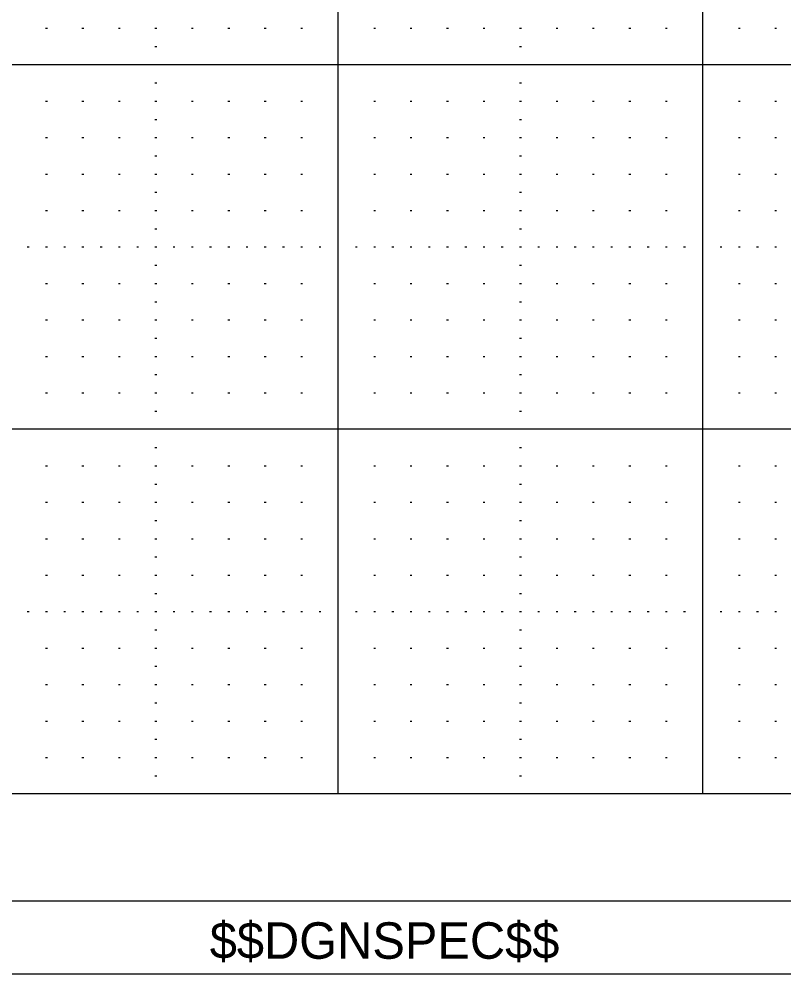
# Model space of a CAD drawing. Extents: x -1.3 to 32.1, y -0.2 to 20.7.
# Drawn here: x 27.87 to 29.967, y -0.2 to 2.418 of the extents above; entities that cross this region are included whole.
import ezdxf

# ---------------------------------------------------------------- set-up
doc = ezdxf.new("R2010")
doc.units = 0
for name, color, linetype in [('Level 1', 7, 'Continuous'), ('Level 37', 7, 'Continuous'), ('Level 4', 7, 'Continuous'), ('Level 48', 7, 'Continuous'), ('Level 5', 7, 'Continuous'), ('Level 62', 7, 'Continuous'), ('Level 63', 7, 'Continuous')]:
    doc.layers.add(name, color=color, linetype=linetype)

msp = doc.modelspace()

# ---------------------------------------------------------------- linework, layer by layer
at = {"layer": 'Level 1'}
msp.add_line((31.617, -0.001), (-0.001, -0.001), dxfattribs=at)
at = {"layer": 'Level 37'}
msp.add_line((30.746, 0.2935), (2.464, 0.2935), dxfattribs=at)
at = {"layer": 'Level 4'}
for p, q in [((28.745, 0.293), (28.745, 10.293)), ((29.745, 0.293), (29.745, 10.293)), ((31.617, 2.293), (-0.001, 2.293)), ((31.617, 1.293), (-0.001, 1.293)), ((31.617, 0.293), (2.463, 0.293))]:
    msp.add_line(p, q, dxfattribs=at)
at = {"layer": 'Level 5'}
for p, q in [((27.9425, 2.393), (27.9475, 2.393)), ((28.0425, 2.393), (28.0475, 2.393)), ((28.1425, 2.393), (28.1475, 2.393)), ((28.2425, 2.393), (28.2475, 2.393)), ((28.3425, 2.393), (28.3475, 2.393)), ((28.4425, 2.393), (28.4475, 2.393)), ((28.5425, 2.393), (28.5475, 2.393)), ((28.6425, 2.393), (28.6475, 2.393)), ((28.8425, 2.393), (28.8475, 2.393)), ((28.9425, 2.393), (28.9475, 2.393)), ((29.0425, 2.393), (29.0475, 2.393)), ((29.1425, 2.393), (29.1475, 2.393)), ((29.2425, 2.393), (29.2475, 2.393)), ((29.3425, 2.393), (29.3475, 2.393)), ((29.4425, 2.393), (29.4475, 2.393)), ((29.5425, 2.393), (29.5475, 2.393)), ((29.6425, 2.393), (29.6475, 2.393)), ((29.8425, 2.393), (29.8475, 2.393)), ((29.9425, 2.393), (29.9475, 2.393)), ((28.2425, 2.343), (28.2475, 2.343)), ((29.2425, 2.343), (29.2475, 2.343)), ((28.2425, 2.243), (28.2475, 2.243)), ((29.2425, 2.243), (29.2475, 2.243)), ((27.9425, 2.193), (27.9475, 2.193)), ((28.0425, 2.193), (28.0475, 2.193)), ((28.1425, 2.193), (28.1475, 2.193)), ((28.2425, 2.193), (28.2475, 2.193)), ((28.3425, 2.193), (28.3475, 2.193)), ((28.4425, 2.193), (28.4475, 2.193)), ((28.5425, 2.193), (28.5475, 2.193)), ((28.6425, 2.193), (28.6475, 2.193)), ((28.8425, 2.193), (28.8475, 2.193)), ((28.9425, 2.193), (28.9475, 2.193)), ((29.0425, 2.193), (29.0475, 2.193)), ((29.1425, 2.193), (29.1475, 2.193)), ((29.2425, 2.193), (29.2475, 2.193)), ((29.3425, 2.193), (29.3475, 2.193)), ((29.4425, 2.193), (29.4475, 2.193)), ((29.5425, 2.193), (29.5475, 2.193)), ((29.6425, 2.193), (29.6475, 2.193)), ((29.8425, 2.193), (29.8475, 2.193)), ((29.9425, 2.193), (29.9475, 2.193)), ((28.2425, 2.143), (28.2475, 2.143)), ((29.2425, 2.143), (29.2475, 2.143)), ((27.9425, 2.093), (27.9475, 2.093)), ((28.0425, 2.093), (28.0475, 2.093)), ((28.1425, 2.093), (28.1475, 2.093)), ((28.2425, 2.093), (28.2475, 2.093)), ((28.3425, 2.093), (28.3475, 2.093)), ((28.4425, 2.093), (28.4475, 2.093)), ((28.5425, 2.093), (28.5475, 2.093)), ((28.6425, 2.093), (28.6475, 2.093)), ((28.8425, 2.093), (28.8475, 2.093)), ((28.9425, 2.093), (28.9475, 2.093)), ((29.0425, 2.093), (29.0475, 2.093)), ((29.1425, 2.093), (29.1475, 2.093)), ((29.2425, 2.093), (29.2475, 2.093)), ((29.3425, 2.093), (29.3475, 2.093)), ((29.4425, 2.093), (29.4475, 2.093)), ((29.5425, 2.093), (29.5475, 2.093)), ((29.6425, 2.093), (29.6475, 2.093)), ((29.8425, 2.093), (29.8475, 2.093)), ((29.9425, 2.093), (29.9475, 2.093)), ((28.2425, 2.043), (28.2475, 2.043)), ((29.2425, 2.043), (29.2475, 2.043)), ((27.9425, 1.993), (27.9475, 1.993)), ((28.0425, 1.993), (28.0475, 1.993)), ((28.1425, 1.993), (28.1475, 1.993)), ((28.2425, 1.993), (28.2475, 1.993)), ((28.3425, 1.993), (28.3475, 1.993)), ((28.4425, 1.993), (28.4475, 1.993)), ((28.5425, 1.993), (28.5475, 1.993)), ((28.6425, 1.993), (28.6475, 1.993)), ((28.8425, 1.993), (28.8475, 1.993)), ((28.9425, 1.993), (28.9475, 1.993)), ((29.0425, 1.993), (29.0475, 1.993)), ((29.1425, 1.993), (29.1475, 1.993)), ((29.2425, 1.993), (29.2475, 1.993)), ((29.3425, 1.993), (29.3475, 1.993)), ((29.4425, 1.993), (29.4475, 1.993)), ((29.5425, 1.993), (29.5475, 1.993)), ((29.6425, 1.993), (29.6475, 1.993)), ((29.8425, 1.993), (29.8475, 1.993)), ((29.9425, 1.993), (29.9475, 1.993)), ((28.2425, 1.943), (28.2475, 1.943)), ((29.2425, 1.943), (29.2475, 1.943)), ((27.9425, 1.893), (27.9475, 1.893)), ((28.0425, 1.893), (28.0475, 1.893)), ((28.1425, 1.893), (28.1475, 1.893)), ((28.2425, 1.893), (28.2475, 1.893)), ((28.3425, 1.893), (28.3475, 1.893)), ((28.4425, 1.893), (28.4475, 1.893)), ((28.5425, 1.893), (28.5475, 1.893)), ((28.6425, 1.893), (28.6475, 1.893)), ((28.8425, 1.893), (28.8475, 1.893)), ((28.9425, 1.893), (28.9475, 1.893)), ((29.0425, 1.893), (29.0475, 1.893)), ((29.1425, 1.893), (29.1475, 1.893)), ((29.2425, 1.893), (29.2475, 1.893)), ((29.3425, 1.893), (29.3475, 1.893)), ((29.4425, 1.893), (29.4475, 1.893)), ((29.5425, 1.893), (29.5475, 1.893)), ((29.6425, 1.893), (29.6475, 1.893)), ((29.8425, 1.893), (29.8475, 1.893)), ((29.9425, 1.893), (29.9475, 1.893)), ((28.2425, 1.843), (28.2475, 1.843)), ((29.2425, 1.843), (29.2475, 1.843)), ((27.8925, 1.793), (27.8975, 1.793)), ((27.9425, 1.793), (27.9475, 1.793)), ((27.9925, 1.793), (27.9975, 1.793)), ((28.0425, 1.793), (28.0475, 1.793)), ((28.0925, 1.793), (28.0975, 1.793)), ((28.1425, 1.793), (28.1475, 1.793)), ((28.1925, 1.793), (28.1975, 1.793)), ((28.2425, 1.793), (28.2475, 1.793)), ((28.2925, 1.793), (28.2975, 1.793)), ((28.3425, 1.793), (28.3475, 1.793)), ((28.3925, 1.793), (28.3975, 1.793)), ((28.4425, 1.793), (28.4475, 1.793)), ((28.4925, 1.793), (28.4975, 1.793)), ((28.5425, 1.793), (28.5475, 1.793)), ((28.5925, 1.793), (28.5975, 1.793)), ((28.6425, 1.793), (28.6475, 1.793)), ((28.6925, 1.793), (28.6975, 1.793)), ((28.7925, 1.793), (28.7975, 1.793)), ((28.8425, 1.793), (28.8475, 1.793)), ((28.8925, 1.793), (28.8975, 1.793)), ((28.9425, 1.793), (28.9475, 1.793)), ((28.9925, 1.793), (28.9975, 1.793)), ((29.0425, 1.793), (29.0475, 1.793)), ((29.0925, 1.793), (29.0975, 1.793)), ((29.1425, 1.793), (29.1475, 1.793)), ((29.1925, 1.793), (29.1975, 1.793)), ((29.2425, 1.793), (29.2475, 1.793)), ((29.2925, 1.793), (29.2975, 1.793)), ((29.3425, 1.793), (29.3475, 1.793)), ((29.3925, 1.793), (29.3975, 1.793)), ((29.4425, 1.793), (29.4475, 1.793)), ((29.4925, 1.793), (29.4975, 1.793)), ((29.5425, 1.793), (29.5475, 1.793)), ((29.5925, 1.793), (29.5975, 1.793)), ((29.6425, 1.793), (29.6475, 1.793)), ((29.6925, 1.793), (29.6975, 1.793)), ((29.7925, 1.793), (29.7975, 1.793)), ((29.8425, 1.793), (29.8475, 1.793)), ((29.8925, 1.793), (29.8975, 1.793)), ((29.9425, 1.793), (29.9475, 1.793)), ((28.2425, 1.743), (28.2475, 1.743)), ((29.2425, 1.743), (29.2475, 1.743)), ((27.9425, 1.693), (27.9475, 1.693)), ((28.0425, 1.693), (28.0475, 1.693)), ((28.1425, 1.693), (28.1475, 1.693)), ((28.2425, 1.693), (28.2475, 1.693)), ((28.3425, 1.693), (28.3475, 1.693)), ((28.4425, 1.693), (28.4475, 1.693)), ((28.5425, 1.693), (28.5475, 1.693)), ((28.6425, 1.693), (28.6475, 1.693)), ((28.8425, 1.693), (28.8475, 1.693)), ((28.9425, 1.693), (28.9475, 1.693)), ((29.0425, 1.693), (29.0475, 1.693)), ((29.1425, 1.693), (29.1475, 1.693)), ((29.2425, 1.693), (29.2475, 1.693)), ((29.3425, 1.693), (29.3475, 1.693)), ((29.4425, 1.693), (29.4475, 1.693)), ((29.5425, 1.693), (29.5475, 1.693)), ((29.6425, 1.693), (29.6475, 1.693)), ((29.8425, 1.693), (29.8475, 1.693)), ((29.9425, 1.693), (29.9475, 1.693)), ((28.2425, 1.643), (28.2475, 1.643)), ((29.2425, 1.643), (29.2475, 1.643)), ((27.9425, 1.593), (27.9475, 1.593)), ((28.0425, 1.593), (28.0475, 1.593)), ((28.1425, 1.593), (28.1475, 1.593)), ((28.2425, 1.593), (28.2475, 1.593)), ((28.3425, 1.593), (28.3475, 1.593)), ((28.4425, 1.593), (28.4475, 1.593)), ((28.5425, 1.593), (28.5475, 1.593)), ((28.6425, 1.593), (28.6475, 1.593)), ((28.8425, 1.593), (28.8475, 1.593)), ((28.9425, 1.593), (28.9475, 1.593)), ((29.0425, 1.593), (29.0475, 1.593)), ((29.1425, 1.593), (29.1475, 1.593)), ((29.2425, 1.593), (29.2475, 1.593)), ((29.3425, 1.593), (29.3475, 1.593)), ((29.4425, 1.593), (29.4475, 1.593)), ((29.5425, 1.593), (29.5475, 1.593)), ((29.6425, 1.593), (29.6475, 1.593)), ((29.8425, 1.593), (29.8475, 1.593)), ((29.9425, 1.593), (29.9475, 1.593)), ((28.2425, 1.543), (28.2475, 1.543)), ((29.2425, 1.543), (29.2475, 1.543)), ((27.9425, 1.493), (27.9475, 1.493)), ((28.0425, 1.493), (28.0475, 1.493)), ((28.1425, 1.493), (28.1475, 1.493)), ((28.2425, 1.493), (28.2475, 1.493)), ((28.3425, 1.493), (28.3475, 1.493)), ((28.4425, 1.493), (28.4475, 1.493)), ((28.5425, 1.493), (28.5475, 1.493)), ((28.6425, 1.493), (28.6475, 1.493)), ((28.8425, 1.493), (28.8475, 1.493)), ((28.9425, 1.493), (28.9475, 1.493)), ((29.0425, 1.493), (29.0475, 1.493)), ((29.1425, 1.493), (29.1475, 1.493)), ((29.2425, 1.493), (29.2475, 1.493)), ((29.3425, 1.493), (29.3475, 1.493)), ((29.4425, 1.493), (29.4475, 1.493)), ((29.5425, 1.493), (29.5475, 1.493)), ((29.6425, 1.493), (29.6475, 1.493)), ((29.8425, 1.493), (29.8475, 1.493)), ((29.9425, 1.493), (29.9475, 1.493)), ((28.2425, 1.443), (28.2475, 1.443)), ((29.2425, 1.443), (29.2475, 1.443)), ((27.9425, 1.393), (27.9475, 1.393)), ((28.0425, 1.393), (28.0475, 1.393)), ((28.1425, 1.393), (28.1475, 1.393)), ((28.2425, 1.393), (28.2475, 1.393)), ((28.3425, 1.393), (28.3475, 1.393)), ((28.4425, 1.393), (28.4475, 1.393)), ((28.5425, 1.393), (28.5475, 1.393)), ((28.6425, 1.393), (28.6475, 1.393)), ((28.8425, 1.393), (28.8475, 1.393)), ((28.9425, 1.393), (28.9475, 1.393)), ((29.0425, 1.393), (29.0475, 1.393)), ((29.1425, 1.393), (29.1475, 1.393)), ((29.2425, 1.393), (29.2475, 1.393)), ((29.3425, 1.393), (29.3475, 1.393)), ((29.4425, 1.393), (29.4475, 1.393)), ((29.5425, 1.393), (29.5475, 1.393)), ((29.6425, 1.393), (29.6475, 1.393)), ((29.8425, 1.393), (29.8475, 1.393)), ((29.9425, 1.393), (29.9475, 1.393)), ((28.2425, 1.343), (28.2475, 1.343)), ((29.2425, 1.343), (29.2475, 1.343)), ((28.2425, 1.243), (28.2475, 1.243)), ((29.2425, 1.243), (29.2475, 1.243)), ((27.9425, 1.193), (27.9475, 1.193)), ((28.0425, 1.193), (28.0475, 1.193)), ((28.1425, 1.193), (28.1475, 1.193)), ((28.2425, 1.193), (28.2475, 1.193)), ((28.3425, 1.193), (28.3475, 1.193)), ((28.4425, 1.193), (28.4475, 1.193)), ((28.5425, 1.193), (28.5475, 1.193)), ((28.6425, 1.193), (28.6475, 1.193)), ((28.8425, 1.193), (28.8475, 1.193)), ((28.9425, 1.193), (28.9475, 1.193)), ((29.0425, 1.193), (29.0475, 1.193)), ((29.1425, 1.193), (29.1475, 1.193)), ((29.2425, 1.193), (29.2475, 1.193)), ((29.3425, 1.193), (29.3475, 1.193)), ((29.4425, 1.193), (29.4475, 1.193)), ((29.5425, 1.193), (29.5475, 1.193)), ((29.6425, 1.193), (29.6475, 1.193)), ((29.8425, 1.193), (29.8475, 1.193)), ((29.9425, 1.193), (29.9475, 1.193)), ((28.2425, 1.143), (28.2475, 1.143)), ((29.2425, 1.143), (29.2475, 1.143)), ((27.9425, 1.093), (27.9475, 1.093)), ((28.0425, 1.093), (28.0475, 1.093)), ((28.1425, 1.093), (28.1475, 1.093)), ((28.2425, 1.093), (28.2475, 1.093)), ((28.3425, 1.093), (28.3475, 1.093)), ((28.4425, 1.093), (28.4475, 1.093)), ((28.5425, 1.093), (28.5475, 1.093)), ((28.6425, 1.093), (28.6475, 1.093)), ((28.8425, 1.093), (28.8475, 1.093)), ((28.9425, 1.093), (28.9475, 1.093)), ((29.0425, 1.093), (29.0475, 1.093)), ((29.1425, 1.093), (29.1475, 1.093)), ((29.2425, 1.093), (29.2475, 1.093)), ((29.3425, 1.093), (29.3475, 1.093)), ((29.4425, 1.093), (29.4475, 1.093)), ((29.5425, 1.093), (29.5475, 1.093)), ((29.6425, 1.093), (29.6475, 1.093)), ((29.8425, 1.093), (29.8475, 1.093)), ((29.9425, 1.093), (29.9475, 1.093)), ((28.2425, 1.043), (28.2475, 1.043)), ((29.2425, 1.043), (29.2475, 1.043)), ((27.9425, 0.993), (27.9475, 0.993)), ((28.0425, 0.993), (28.0475, 0.993)), ((28.1425, 0.993), (28.1475, 0.993)), ((28.2425, 0.993), (28.2475, 0.993)), ((28.3425, 0.993), (28.3475, 0.993)), ((28.4425, 0.993), (28.4475, 0.993)), ((28.5425, 0.993), (28.5475, 0.993)), ((28.6425, 0.993), (28.6475, 0.993)), ((28.8425, 0.993), (28.8475, 0.993)), ((28.9425, 0.993), (28.9475, 0.993)), ((29.0425, 0.993), (29.0475, 0.993)), ((29.1425, 0.993), (29.1475, 0.993)), ((29.2425, 0.993), (29.2475, 0.993)), ((29.3425, 0.993), (29.3475, 0.993)), ((29.4425, 0.993), (29.4475, 0.993)), ((29.5425, 0.993), (29.5475, 0.993)), ((29.6425, 0.993), (29.6475, 0.993)), ((29.8425, 0.993), (29.8475, 0.993)), ((29.9425, 0.993), (29.9475, 0.993)), ((28.2425, 0.943), (28.2475, 0.943)), ((29.2425, 0.943), (29.2475, 0.943)), ((27.9425, 0.893), (27.9475, 0.893)), ((28.0425, 0.893), (28.0475, 0.893)), ((28.1425, 0.893), (28.1475, 0.893)), ((28.2425, 0.893), (28.2475, 0.893)), ((28.3425, 0.893), (28.3475, 0.893)), ((28.4425, 0.893), (28.4475, 0.893)), ((28.5425, 0.893), (28.5475, 0.893)), ((28.6425, 0.893), (28.6475, 0.893)), ((28.8425, 0.893), (28.8475, 0.893)), ((28.9425, 0.893), (28.9475, 0.893)), ((29.0425, 0.893), (29.0475, 0.893)), ((29.1425, 0.893), (29.1475, 0.893)), ((29.2425, 0.893), (29.2475, 0.893)), ((29.3425, 0.893), (29.3475, 0.893)), ((29.4425, 0.893), (29.4475, 0.893)), ((29.5425, 0.893), (29.5475, 0.893)), ((29.6425, 0.893), (29.6475, 0.893)), ((29.8425, 0.893), (29.8475, 0.893)), ((29.9425, 0.893), (29.9475, 0.893)), ((28.2425, 0.843), (28.2475, 0.843)), ((29.2425, 0.843), (29.2475, 0.843)), ((27.8925, 0.793), (27.8975, 0.793)), ((27.9425, 0.793), (27.9475, 0.793)), ((27.9925, 0.793), (27.9975, 0.793)), ((28.0425, 0.793), (28.0475, 0.793)), ((28.0925, 0.793), (28.0975, 0.793)), ((28.1425, 0.793), (28.1475, 0.793)), ((28.1925, 0.793), (28.1975, 0.793)), ((28.2425, 0.793), (28.2475, 0.793)), ((28.2925, 0.793), (28.2975, 0.793)), ((28.3425, 0.793), (28.3475, 0.793)), ((28.3925, 0.793), (28.3975, 0.793)), ((28.4425, 0.793), (28.4475, 0.793)), ((28.4925, 0.793), (28.4975, 0.793)), ((28.5425, 0.793), (28.5475, 0.793)), ((28.5925, 0.793), (28.5975, 0.793)), ((28.6425, 0.793), (28.6475, 0.793)), ((28.6925, 0.793), (28.6975, 0.793)), ((28.7925, 0.793), (28.7975, 0.793)), ((28.8425, 0.793), (28.8475, 0.793)), ((28.8925, 0.793), (28.8975, 0.793)), ((28.9425, 0.793), (28.9475, 0.793)), ((28.9925, 0.793), (28.9975, 0.793)), ((29.0425, 0.793), (29.0475, 0.793)), ((29.0925, 0.793), (29.0975, 0.793)), ((29.1425, 0.793), (29.1475, 0.793)), ((29.1925, 0.793), (29.1975, 0.793)), ((29.2425, 0.793), (29.2475, 0.793)), ((29.2925, 0.793), (29.2975, 0.793)), ((29.3425, 0.793), (29.3475, 0.793)), ((29.3925, 0.793), (29.3975, 0.793)), ((29.4425, 0.793), (29.4475, 0.793)), ((29.4925, 0.793), (29.4975, 0.793)), ((29.5425, 0.793), (29.5475, 0.793)), ((29.5925, 0.793), (29.5975, 0.793)), ((29.6425, 0.793), (29.6475, 0.793)), ((29.6925, 0.793), (29.6975, 0.793)), ((29.7925, 0.793), (29.7975, 0.793)), ((29.8425, 0.793), (29.8475, 0.793)), ((29.8925, 0.793), (29.8975, 0.793)), ((29.9425, 0.793), (29.9475, 0.793)), ((28.2425, 0.743), (28.2475, 0.743)), ((29.2425, 0.743), (29.2475, 0.743)), ((27.9425, 0.693), (27.9475, 0.693)), ((28.0425, 0.693), (28.0475, 0.693)), ((28.1425, 0.693), (28.1475, 0.693)), ((28.2425, 0.693), (28.2475, 0.693)), ((28.3425, 0.693), (28.3475, 0.693)), ((28.4425, 0.693), (28.4475, 0.693)), ((28.5425, 0.693), (28.5475, 0.693)), ((28.6425, 0.693), (28.6475, 0.693)), ((28.8425, 0.693), (28.8475, 0.693)), ((28.9425, 0.693), (28.9475, 0.693)), ((29.0425, 0.693), (29.0475, 0.693)), ((29.1425, 0.693), (29.1475, 0.693)), ((29.2425, 0.693), (29.2475, 0.693)), ((29.3425, 0.693), (29.3475, 0.693)), ((29.4425, 0.693), (29.4475, 0.693)), ((29.5425, 0.693), (29.5475, 0.693)), ((29.6425, 0.693), (29.6475, 0.693)), ((29.8425, 0.693), (29.8475, 0.693)), ((29.9425, 0.693), (29.9475, 0.693)), ((28.2425, 0.643), (28.2475, 0.643)), ((29.2425, 0.643), (29.2475, 0.643)), ((27.9425, 0.593), (27.9475, 0.593)), ((28.0425, 0.593), (28.0475, 0.593)), ((28.1425, 0.593), (28.1475, 0.593)), ((28.2425, 0.593), (28.2475, 0.593)), ((28.3425, 0.593), (28.3475, 0.593)), ((28.4425, 0.593), (28.4475, 0.593)), ((28.5425, 0.593), (28.5475, 0.593)), ((28.6425, 0.593), (28.6475, 0.593)), ((28.8425, 0.593), (28.8475, 0.593)), ((28.9425, 0.593), (28.9475, 0.593)), ((29.0425, 0.593), (29.0475, 0.593)), ((29.1425, 0.593), (29.1475, 0.593)), ((29.2425, 0.593), (29.2475, 0.593)), ((29.3425, 0.593), (29.3475, 0.593)), ((29.4425, 0.593), (29.4475, 0.593)), ((29.5425, 0.593), (29.5475, 0.593)), ((29.6425, 0.593), (29.6475, 0.593)), ((29.8425, 0.593), (29.8475, 0.593)), ((29.9425, 0.593), (29.9475, 0.593)), ((28.2425, 0.543), (28.2475, 0.543)), ((29.2425, 0.543), (29.2475, 0.543)), ((27.9425, 0.493), (27.9475, 0.493)), ((28.0425, 0.493), (28.0475, 0.493)), ((28.1425, 0.493), (28.1475, 0.493)), ((28.2425, 0.493), (28.2475, 0.493)), ((28.3425, 0.493), (28.3475, 0.493)), ((28.4425, 0.493), (28.4475, 0.493)), ((28.5425, 0.493), (28.5475, 0.493)), ((28.6425, 0.493), (28.6475, 0.493)), ((28.8425, 0.493), (28.8475, 0.493)), ((28.9425, 0.493), (28.9475, 0.493)), ((29.0425, 0.493), (29.0475, 0.493)), ((29.1425, 0.493), (29.1475, 0.493)), ((29.2425, 0.493), (29.2475, 0.493)), ((29.3425, 0.493), (29.3475, 0.493)), ((29.4425, 0.493), (29.4475, 0.493)), ((29.5425, 0.493), (29.5475, 0.493)), ((29.6425, 0.493), (29.6475, 0.493)), ((29.8425, 0.493), (29.8475, 0.493)), ((29.9425, 0.493), (29.9475, 0.493)), ((28.2425, 0.443), (28.2475, 0.443)), ((29.2425, 0.443), (29.2475, 0.443)), ((27.9425, 0.393), (27.9475, 0.393)), ((28.0425, 0.393), (28.0475, 0.393)), ((28.1425, 0.393), (28.1475, 0.393)), ((28.2425, 0.393), (28.2475, 0.393)), ((28.3425, 0.393), (28.3475, 0.393)), ((28.4425, 0.393), (28.4475, 0.393)), ((28.5425, 0.393), (28.5475, 0.393)), ((28.6425, 0.393), (28.6475, 0.393)), ((28.8425, 0.393), (28.8475, 0.393)), ((28.9425, 0.393), (28.9475, 0.393)), ((29.0425, 0.393), (29.0475, 0.393)), ((29.1425, 0.393), (29.1475, 0.393)), ((29.2425, 0.393), (29.2475, 0.393)), ((29.3425, 0.393), (29.3475, 0.393)), ((29.4425, 0.393), (29.4475, 0.393)), ((29.5425, 0.393), (29.5475, 0.393)), ((29.6425, 0.393), (29.6475, 0.393)), ((29.8425, 0.393), (29.8475, 0.393)), ((29.9425, 0.393), (29.9475, 0.393)), ((28.2425, 0.343), (28.2475, 0.343)), ((29.2425, 0.343), (29.2475, 0.343))]:
    msp.add_line(p, q, dxfattribs=at)
at = {"layer": 'Level 62'}
msp.add_line((2.4642, 0), (31.618, 0), dxfattribs=at)
at = {"layer": 'Level 63'}
msp.add_lwpolyline([(-1.263, -0.2005), (32.067, -0.2005), (32.067, 20.7465), (-1.263, 20.7465)], close=True, dxfattribs=at)

# ---------------------------------------------------------------- texts
at = {"layer": 'Level 48'}
msp.add_text('$$DGNSPEC$$', height=0.100002, dxfattribs=at).set_placement((28.3929, -0.159))

doc.saveas('drawing.dxf')
